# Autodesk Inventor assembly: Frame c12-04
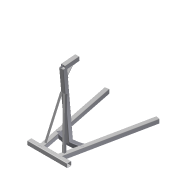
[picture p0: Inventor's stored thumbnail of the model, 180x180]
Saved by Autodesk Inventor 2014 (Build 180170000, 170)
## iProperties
Created: 2011-01
Part Number: Frame c12-04
Document SubType Name: Assembly
Designer: Thom Tremblay
_FrameDoc: Frame Assembly
_Version: 15.0.0
Author: Thom Tremblay
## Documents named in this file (20)
- C:\Inventor 2014 Essentials\Assemblies\Chapter 12\Frame\Frame c12-04.iam
- C:\Inventor 2014 Essentials\Assemblies\Chapter 12\Frame\Skeleton-c12-04.ipt
- C:\Inventor 2014 Essentials\Assemblies\Chapter 12\Frame\ANSI 3x3x3_16 00000013.ipt
- ANSI 3x3x3_16 00000013.ipt
- C:\Inventor 2014 Essentials\Assemblies\Chapter 12\Frame\ANSI 3x3x3_16 00000014.ipt
- ANSI 3x3x3_16 00000014.ipt
- C:\Inventor 2014 Essentials\Assemblies\Chapter 12\Frame\ANSI 3x3x3_16 00000015.ipt
- ANSI 3x3x3_16 00000015.ipt
- C:\Inventor 2014 Essentials\Assemblies\Chapter 12\Frame\ANSI 3x3x3_16 00000016.ipt
- ANSI 3x3x3_16 00000016.ipt
- C:\Inventor 2014 Essentials\Assemblies\Chapter 12\Frame\ANSI 3x3x3_16 00000017.ipt
- ANSI 3x3x3_16 00000017.ipt
- C:\Inventor 2014 Essentials\Assemblies\Chapter 12\Frame\ANSI L 1.5 x 1.5 x 3_16 00000019.ipt
- ANSI L 1.5 x 1.5 x 3_16 00000019.ipt
- C:\Inventor 2014 Essentials\Assemblies\Chapter 12\Frame\ANSI L 1.5 x 1.5 x 3_16 00000020.ipt
- ANSI L 1.5 x 1.5 x 3_16 00000020.ipt
- C:\Inventor 2014 Essentials\Assemblies\Chapter 12\Frame\ANSI 2 1_4x5_16 00000021.ipt
- ANSI 2 1_4x5_16 00000021.ipt
- C:\Inventor 2014 Essentials\Assemblies\Chapter 12\Frame\ANSI 3x3x3_16 00000057.ipt
- ANSI 3x3x3_16 00000057.ipt
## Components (10 placed, 10 different names)
1. Frame Reference Model
2. ANSI 3x3x3_16 00000013:1
3. ANSI 3x3x3_16 00000014:1
4. ANSI 3x3x3_16 00000015:1
5. ANSI 3x3x3_16 00000016:1
6. ANSI 3x3x3_16 00000017:1
7. ANSI L 1.5 x 1.5 x 3_16 00000019:1
8. ANSI L 1.5 x 1.5 x 3_16 00000020:1
9. ANSI 2 1_4x5_16 00000021:1
10. ANSI 3x3x3_16 00000057:1
